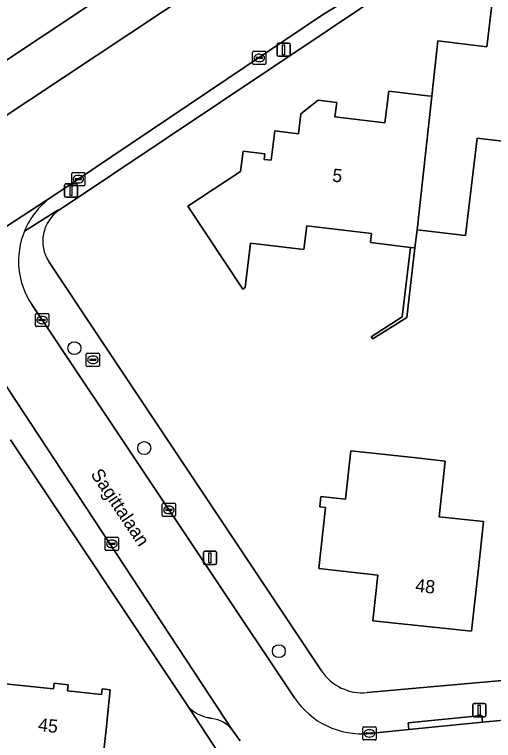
# Model space of a CAD drawing. Extents: x 162396 to 163643, y 386452 to 387406.
# Drawn here: x 163062.6 to 163098.8, y 386719.3 to 386774.2 of the extents above; entities that cross this region are included whole.
import ezdxf

# ---------------------------------------------------------------- set-up
doc = ezdxf.new("R2010")
doc.units = 0
for name, color, linetype in [('IMGEO_Boom', 7, 'Continuous'), ('IMGEO_Brandkraan', 7, 'Continuous'), ('IMGEO_Erf', 7, 'Continuous'), ('IMGEO_Kolk', 7, 'Continuous'), ('IMGEO_Lichtmast', 7, 'Continuous'), ('IMGEO_Muur', 7, 'Continuous'), ('IMGEO_Openbare_ruimte_label', 7, 'Continuous'), ('IMGEO_Pand', 7, 'Continuous'), ('IMGEO_Pand_nummerreeks', 7, 'Continuous'), ('IMGEO_Parkeervlak_open', 7, 'Continuous'), ('IMGEO_Rijbaan_lokaal_gesloten', 7, 'Continuous'), ('IMGEO_Rijbaan_lokaal_open', 7, 'Continuous'), ('IMGEO_Voetpad_open', 7, 'Continuous')]:
    doc.layers.add(name, color=color, linetype=linetype)

msp = doc.modelspace()

# ---------------------------------------------------------------- linework, layer by layer
at = {"layer": 'IMGEO_Boom'}
for centre in [(163067.103, 386748.994), (163072.383, 386741.433), (163082.556, 386726.071)]:
    msp.add_circle(centre, 0.489, dxfattribs=at)
at = {"layer": 'IMGEO_Brandkraan'}
for p, q in [((163068.004, 386747.688), (163068.004, 386748.54)), ((163068.079, 386748.614), (163068.931, 386748.614)), ((163068.263, 386748.108), (163068.263, 386748.12)), ((163068.306, 386748.157), (163068.704, 386748.157)), ((163068.492, 386748.394), (163068.517, 386748.394)), ((163068.747, 386748.12), (163068.747, 386748.108)), ((163069.005, 386748.54), (163069.005, 386747.688)), ((163068.931, 386747.614), (163068.079, 386747.614)), ((163068.701, 386748.071), (163068.303, 386748.071)), ((163068.515, 386747.834), (163068.49, 386747.834))]:
    msp.add_line(p, q, dxfattribs=at)
for points in [[(163068.004, 386747.688), (163068.004, 386748.54)], [(163068.079, 386748.614), (163068.931, 386748.614)], [(163069.005, 386748.54), (163069.005, 386747.688)], [(163068.931, 386747.614), (163068.079, 386747.614)]]:
    msp.add_lwpolyline(points, dxfattribs=at)
for centre, radius, start, end in [((163068.081, 386748.538), 0.0765, 91.552, 178.448), ((163068.081, 386748.538), 0.0765, 91.552, 178.448), ((163068.303, 386748.117), 0.0403, 85.8775, 175.7526), ((163068.3, 386748.107), 0.0366, 178.938, 274.7102), ((163068.704, 386748.114), 0.043, 264.8664, 352.4533), ((163068.708, 386748.119), 0.0386, 1.7309, 96.639), ((163068.929, 386748.538), 0.0765, 1.552, 88.448), ((163068.929, 386748.538), 0.0765, 1.552, 88.448), ((163068.081, 386747.69), 0.0765, 181.552, 268.448), ((163068.081, 386747.69), 0.0765, 181.552, 268.448), ((163068.929, 386747.69), 0.0765, 271.552, 358.448), ((163068.929, 386747.69), 0.0765, 271.552, 358.448)]:
    msp.add_arc(centre, radius, start, end, dxfattribs=at)
for centre, major_axis, ratio, start_param, end_param in [((163068.491, 386748.114), (-0.387, 0.002), 0.722429, 4.712389, 7.853982), ((163068.516, 386748.114), (-0.39, 0.002), 0.717154, 1.570796, 4.712389)]:
    msp.add_ellipse(centre, major_axis=major_axis, ratio=ratio, start_param=start_param, end_param=end_param, dxfattribs=at)
at = {"layer": 'IMGEO_Erf'}
for points in [[(162983.26, 386826.659), (162939.497, 386855.132), (162935.841, 386824.556), (162935.369, 386820.614), (162931.696, 386789.898), (162994.075, 386750), (163000, 386746.21), (163010.632, 386739.479), (163010.94, 386739.303), (163011.262, 386739.156), (163011.596, 386739.037), (163011.94, 386738.949), (163012.29, 386738.893), (163012.643, 386738.867), (163012.998, 386738.873), (163013.35, 386738.911), (163013.698, 386738.981), (163014.038, 386739.081), (163014.368, 386739.211), (163014.685, 386739.37), (163014.944, 386739.528), (163030.691, 386750), (163094.938, 386792.726)], [(163227.316, 386699.623), (163227.044, 386700.095), (163212.434, 386723.369), (163194.869, 386749.748), (163193.027, 386752.59), (163166.953, 386791.514), (163151.55, 386814.685), (163151.264, 386814.81), (163150.968, 386814.908), (163150.664, 386814.98), (163150.356, 386815.024), (163150.044, 386815.041), (163149.732, 386815.03), (163149.422, 386814.99), (163149.118, 386814.924), (163148.82, 386814.83), (163148.532, 386814.71), (163148.255, 386814.565), (163148.07, 386814.449), (163146.898, 386813.664), (163065.982, 386759.453)], [(163101.577, 386764.413), (163097.541, 386764.869), (163096.663, 386757.522), (163093.013, 386757.959), (163092.848, 386756.574), (163092.221, 386751.327), (163089.656, 386749.699), (163089.531, 386749.856), (163091.873, 386751.371), (163092.499, 386756.616), (163089.491, 386756.976), (163089.574, 386757.666), (163084.667, 386758.252), (163084.452, 386756.458), (163080.41, 386756.941), (163080.009, 386753.583), (163079.836, 386753.446), (163075.679, 386759.73), (163079.668, 386762.37), (163079.851, 386763.903), (163081.509, 386763.705), (163081.458, 386763.276), (163081.985, 386763.213), (163082.25, 386765.425), (163084.046, 386765.21), (163084.226, 386766.719), (163085.541, 386767.753), (163086.93, 386767.587), (163086.798, 386766.485), (163090.575, 386766.034), (163090.862, 386768.441), (163093.794, 386768.09), (163094.119, 386768.051), (163094.578, 386772.239), (163098.281, 386771.797), (163098.656, 386774.94)], [(163065.193, 386755.51), (163068.861, 386750), (163085.772, 386724.593)], [(163079.49, 386716.116), (163075.748, 386721.818), (163062.275, 386742.065)], [(163089.245, 386722.934), (163135.707, 386727.073)]]:
    msp.add_lwpolyline(points, dxfattribs=at)
for points in [[(163089.655, 386728.373), (163090.047, 386731.833), (163085.572, 386732.322), (163086.076, 386736.936), (163085.654, 386736.982), (163085.739, 386737.761), (163087.59, 386737.559), (163087.99, 386741.229), (163092.961, 386740.686), (163095.123, 386740.45), (163094.664, 386736.24), (163098.028, 386735.872), (163097.666, 386732.551), (163097.123, 386727.58)], [(163065.533, 386723.218), (163065.578, 386723.647), (163066.633, 386723.535), (163066.583, 386723.071), (163069.161, 386722.797), (163069.206, 386723.215), (163069.813, 386723.151), (163069.493, 386720.139), (163069.037, 386715.858), (163072.81, 386715.457), (163072.282, 386710.486), (163071.997, 386707.809), (163065.544, 386708.495), (163064.933, 386708.56), (163064.113, 386708.215), (163060.514, 386708.598), (163059.694, 386709.117), (163060.077, 386712.718), (163060.759, 386719.132), (163061.288, 386724.103), (163061.917, 386724.036), (163061.872, 386723.607)]]:
    msp.add_lwpolyline(points, close=True, dxfattribs=at)
for centre, radius, start, end in [((163067.559, 386757.087), 2.844, 123.6894, 213.6795), ((163088.899, 386726.675), 3.757, 213.6571, 275.2767)]:
    msp.add_arc(centre, radius, start, end, dxfattribs=at)
at = {"layer": 'IMGEO_Kolk'}
for p, q in [((163080.579, 386770.528), (163080.579, 386771.38)), ((163080.654, 386771.454), (163081.506, 386771.454)), ((163081.067, 386771.234), (163081.092, 386771.234)), ((163081.58, 386771.38), (163081.58, 386770.528)), ((163080.838, 386770.948), (163080.838, 386770.96)), ((163081.276, 386770.911), (163080.878, 386770.911)), ((163080.881, 386770.997), (163081.279, 386770.997)), ((163081.09, 386770.674), (163081.065, 386770.674)), ((163081.322, 386770.96), (163081.322, 386770.948)), ((163081.506, 386770.454), (163080.654, 386770.454)), ((163066.901, 386761.357), (163066.901, 386762.209)), ((163066.976, 386762.283), (163067.828, 386762.283)), ((163067.203, 386761.826), (163067.601, 386761.826)), ((163067.389, 386762.063), (163067.414, 386762.063)), ((163067.902, 386762.209), (163067.902, 386761.357)), ((163067.828, 386761.283), (163066.976, 386761.283)), ((163067.16, 386761.777), (163067.16, 386761.789)), ((163067.598, 386761.74), (163067.2, 386761.74)), ((163067.412, 386761.503), (163067.387, 386761.503)), ((163067.644, 386761.789), (163067.644, 386761.777)), ((163064.164, 386750.697), (163064.164, 386751.549)), ((163064.239, 386751.623), (163065.091, 386751.623)), ((163064.652, 386751.403), (163064.677, 386751.403)), ((163065.165, 386751.549), (163065.165, 386750.697)), ((163064.423, 386751.117), (163064.423, 386751.129)), ((163064.861, 386751.08), (163064.463, 386751.08)), ((163064.466, 386751.166), (163064.864, 386751.166)), ((163064.675, 386750.843), (163064.65, 386750.843)), ((163064.907, 386751.129), (163064.907, 386751.117)), ((163065.091, 386750.623), (163064.239, 386750.623)), ((163073.751, 386736.334), (163073.751, 386737.186)), ((163073.826, 386737.26), (163074.678, 386737.26)), ((163074.752, 386737.186), (163074.752, 386736.334)), ((163074.01, 386736.754), (163074.01, 386736.766)), ((163074.448, 386736.717), (163074.05, 386736.717)), ((163074.053, 386736.803), (163074.451, 386736.803)), ((163074.239, 386737.04), (163074.264, 386737.04)), ((163074.494, 386736.766), (163074.494, 386736.754)), ((163074.678, 386736.26), (163073.826, 386736.26)), ((163074.262, 386736.48), (163074.237, 386736.48)), ((163069.441, 386733.764), (163069.441, 386734.616)), ((163069.516, 386734.69), (163070.368, 386734.69)), ((163069.929, 386734.47), (163069.954, 386734.47)), ((163070.442, 386734.616), (163070.442, 386733.764)), ((163069.7, 386734.184), (163069.7, 386734.196)), ((163070.138, 386734.147), (163069.74, 386734.147)), ((163069.743, 386734.233), (163070.141, 386734.233)), ((163069.952, 386733.91), (163069.927, 386733.91)), ((163070.184, 386734.196), (163070.184, 386734.184)), ((163070.368, 386733.69), (163069.516, 386733.69)), ((163088.904, 386719.426), (163088.904, 386720.278)), ((163088.979, 386720.352), (163089.831, 386720.352)), ((163089.392, 386720.132), (163089.417, 386720.132)), ((163089.905, 386720.278), (163089.905, 386719.426)), ((163089.163, 386719.846), (163089.163, 386719.858)), ((163089.601, 386719.809), (163089.203, 386719.809)), ((163089.206, 386719.895), (163089.604, 386719.895)), ((163089.415, 386719.572), (163089.39, 386719.572)), ((163089.647, 386719.858), (163089.647, 386719.846)), ((163089.831, 386719.352), (163088.979, 386719.352))]:
    msp.add_line(p, q, dxfattribs=at)
for points in [[(163080.579, 386770.528), (163080.579, 386771.38)], [(163080.654, 386771.454), (163081.506, 386771.454)], [(163081.58, 386771.38), (163081.58, 386770.528)], [(163081.506, 386770.454), (163080.654, 386770.454)], [(163066.901, 386761.357), (163066.901, 386762.209)], [(163066.976, 386762.283), (163067.828, 386762.283)], [(163067.902, 386762.209), (163067.902, 386761.357)], [(163067.828, 386761.283), (163066.976, 386761.283)], [(163064.164, 386750.697), (163064.164, 386751.549)], [(163064.239, 386751.623), (163065.091, 386751.623)], [(163065.165, 386751.549), (163065.165, 386750.697)], [(163065.091, 386750.623), (163064.239, 386750.623)], [(163073.751, 386736.334), (163073.751, 386737.186)], [(163073.826, 386737.26), (163074.678, 386737.26)], [(163074.752, 386737.186), (163074.752, 386736.334)], [(163074.678, 386736.26), (163073.826, 386736.26)], [(163069.441, 386733.764), (163069.441, 386734.616)], [(163069.516, 386734.69), (163070.368, 386734.69)], [(163070.442, 386734.616), (163070.442, 386733.764)], [(163070.368, 386733.69), (163069.516, 386733.69)], [(163088.904, 386719.426), (163088.904, 386720.278)], [(163088.979, 386720.352), (163089.831, 386720.352)], [(163089.905, 386720.278), (163089.905, 386719.426)], [(163089.831, 386719.352), (163088.979, 386719.352)]]:
    msp.add_lwpolyline(points, dxfattribs=at)
for centre, radius, start, end in [((163080.656, 386771.378), 0.0765, 91.552, 178.448), ((163080.656, 386771.378), 0.0765, 91.552, 178.448), ((163081.504, 386771.378), 0.0765, 1.552, 88.448), ((163081.504, 386771.378), 0.0765, 1.552, 88.448), ((163080.878, 386770.957), 0.0403, 85.8775, 175.7526), ((163080.875, 386770.947), 0.0366, 178.938, 274.7102), ((163081.279, 386770.954), 0.043, 264.8664, 352.4533), ((163081.283, 386770.959), 0.0386, 1.7309, 96.639), ((163080.656, 386770.53), 0.0765, 181.552, 268.448), ((163080.656, 386770.53), 0.0765, 181.552, 268.448), ((163081.504, 386770.53), 0.0765, 271.552, 358.448), ((163081.504, 386770.53), 0.0765, 271.552, 358.448), ((163066.978, 386762.207), 0.0765, 91.552, 178.448), ((163066.978, 386762.207), 0.0765, 91.552, 178.448), ((163067.2, 386761.786), 0.0403, 85.8775, 175.7526), ((163067.605, 386761.788), 0.0386, 1.7309, 96.639), ((163067.826, 386762.207), 0.0765, 1.552, 88.448), ((163067.826, 386762.207), 0.0765, 1.552, 88.448), ((163066.978, 386761.359), 0.0765, 181.552, 268.448), ((163066.978, 386761.359), 0.0765, 181.552, 268.448), ((163067.197, 386761.776), 0.0366, 178.938, 274.7102), ((163067.601, 386761.783), 0.043, 264.8664, 352.4533), ((163067.826, 386761.359), 0.0765, 271.552, 358.448), ((163067.826, 386761.359), 0.0765, 271.552, 358.448), ((163064.241, 386751.547), 0.0765, 91.552, 178.448), ((163064.241, 386751.547), 0.0765, 91.552, 178.448), ((163065.089, 386751.547), 0.0765, 1.552, 88.448), ((163065.089, 386751.547), 0.0765, 1.552, 88.448), ((163064.463, 386751.126), 0.0403, 85.8775, 175.7526), ((163064.46, 386751.116), 0.0366, 178.938, 274.7102), ((163064.864, 386751.123), 0.043, 264.8664, 352.4533), ((163064.868, 386751.128), 0.0386, 1.7309, 96.639), ((163064.241, 386750.699), 0.0765, 181.552, 268.448), ((163064.241, 386750.699), 0.0765, 181.552, 268.448), ((163065.089, 386750.699), 0.0765, 271.552, 358.448), ((163065.089, 386750.699), 0.0765, 271.552, 358.448), ((163073.828, 386737.184), 0.0765, 91.552, 178.448), ((163073.828, 386737.184), 0.0765, 91.552, 178.448), ((163074.676, 386737.184), 0.0765, 1.552, 88.448), ((163074.676, 386737.184), 0.0765, 1.552, 88.448), ((163074.05, 386736.763), 0.0403, 85.8775, 175.7526), ((163074.047, 386736.753), 0.0366, 178.938, 274.7102), ((163074.451, 386736.76), 0.043, 264.8664, 352.4533), ((163074.455, 386736.765), 0.0386, 1.7309, 96.639), ((163073.828, 386736.336), 0.0765, 181.552, 268.448), ((163073.828, 386736.336), 0.0765, 181.552, 268.448), ((163074.676, 386736.336), 0.0765, 271.552, 358.448), ((163074.676, 386736.336), 0.0765, 271.552, 358.448), ((163069.518, 386734.614), 0.0765, 91.552, 178.448), ((163069.518, 386734.614), 0.0765, 91.552, 178.448), ((163070.366, 386734.614), 0.0765, 1.552, 88.448), ((163070.366, 386734.614), 0.0765, 1.552, 88.448), ((163069.74, 386734.193), 0.0403, 85.8775, 175.7526), ((163069.737, 386734.183), 0.0366, 178.938, 274.7102), ((163070.141, 386734.19), 0.043, 264.8664, 352.4533), ((163070.145, 386734.195), 0.0386, 1.7309, 96.639), ((163069.518, 386733.766), 0.0765, 181.552, 268.448), ((163069.518, 386733.766), 0.0765, 181.552, 268.448), ((163070.366, 386733.766), 0.0765, 271.552, 358.448), ((163070.366, 386733.766), 0.0765, 271.552, 358.448), ((163088.981, 386720.276), 0.0765, 91.552, 178.448), ((163088.981, 386720.276), 0.0765, 91.552, 178.448), ((163089.829, 386720.276), 0.0765, 1.552, 88.448), ((163089.829, 386720.276), 0.0765, 1.552, 88.448), ((163089.203, 386719.855), 0.0403, 85.8775, 175.7526), ((163089.2, 386719.845), 0.0366, 178.938, 274.7102), ((163089.604, 386719.852), 0.043, 264.8664, 352.4533), ((163089.608, 386719.857), 0.0386, 1.7309, 96.639), ((163088.981, 386719.428), 0.0765, 181.552, 268.448), ((163088.981, 386719.428), 0.0765, 181.552, 268.448), ((163089.829, 386719.428), 0.0765, 271.552, 358.448), ((163089.829, 386719.428), 0.0765, 271.552, 358.448)]:
    msp.add_arc(centre, radius, start, end, dxfattribs=at)
for centre, major_axis, ratio, start_param, end_param in [((163081.066, 386770.954), (-0.387, 0.002), 0.722429, 4.712389, 7.853982), ((163081.091, 386770.954), (-0.39, 0.002), 0.717154, 1.570796, 4.712389), ((163067.388, 386761.783), (-0.387, 0.002), 0.722429, 4.712389, 7.853982), ((163067.413, 386761.783), (-0.39, 0.002), 0.717154, 1.570796, 4.712389), ((163064.651, 386751.123), (-0.387, 0.002), 0.722429, 4.712389, 7.853982), ((163064.676, 386751.123), (-0.39, 0.002), 0.717154, 1.570796, 4.712389), ((163074.238, 386736.76), (-0.387, 0.002), 0.722429, 4.712389, 7.853982), ((163074.263, 386736.76), (-0.39, 0.002), 0.717154, 1.570796, 4.712389), ((163069.928, 386734.19), (-0.387, 0.002), 0.722429, 4.712389, 7.853982), ((163069.953, 386734.19), (-0.39, 0.002), 0.717154, 1.570796, 4.712389), ((163089.391, 386719.852), (-0.387, 0.002), 0.722429, 4.712389, 7.853982), ((163089.416, 386719.852), (-0.39, 0.002), 0.717154, 1.570796, 4.712389)]:
    msp.add_ellipse(centre, major_axis=major_axis, ratio=ratio, start_param=start_param, end_param=end_param, dxfattribs=at)
at = {"layer": 'IMGEO_Lichtmast'}
for p, q in [((163082.424, 386771.173), (163082.424, 386771.973)), ((163082.424, 386771.973), (163082.424, 386771.173)), ((163082.524, 386772.073), (163083.314, 386772.073)), ((163083.314, 386772.073), (163082.524, 386772.073)), ((163083.414, 386771.973), (163083.414, 386771.173)), ((163083.414, 386771.173), (163083.414, 386771.973)), ((163083.314, 386771.073), (163082.524, 386771.073)), ((163082.524, 386771.073), (163083.314, 386771.073)), ((163066.352, 386760.518), (163066.352, 386761.318)), ((163066.352, 386761.318), (163066.352, 386760.518)), ((163066.452, 386761.418), (163067.242, 386761.418)), ((163067.242, 386761.418), (163066.452, 386761.418)), ((163067.342, 386761.318), (163067.342, 386760.518)), ((163067.342, 386760.518), (163067.342, 386761.318)), ((163067.242, 386760.418), (163066.452, 386760.418)), ((163066.452, 386760.418), (163067.242, 386760.418)), ((163076.856, 386732.728), (163076.856, 386733.528)), ((163076.856, 386733.528), (163076.856, 386732.728)), ((163076.956, 386733.628), (163077.746, 386733.628)), ((163077.746, 386733.628), (163076.956, 386733.628)), ((163077.846, 386733.528), (163077.846, 386732.728)), ((163077.846, 386732.728), (163077.846, 386733.528)), ((163077.746, 386732.628), (163076.956, 386732.628)), ((163076.956, 386732.628), (163077.746, 386732.628)), ((163097.209, 386721.208), (163097.209, 386722.008)), ((163097.209, 386722.008), (163097.209, 386721.208)), ((163097.309, 386722.108), (163098.099, 386722.108)), ((163098.099, 386722.108), (163097.309, 386722.108)), ((163098.199, 386722.008), (163098.199, 386721.208)), ((163098.199, 386721.208), (163098.199, 386722.008)), ((163098.099, 386721.108), (163097.309, 386721.108)), ((163097.309, 386721.108), (163098.099, 386721.108))]:
    msp.add_line(p, q, dxfattribs=at)
for points in [[(163082.844, 386771.948), (163082.994, 386771.948), (163082.994, 386771.198), (163082.844, 386771.198), (163082.844, 386771.948)], [(163066.772, 386761.293), (163066.922, 386761.293), (163066.922, 386760.543), (163066.772, 386760.543), (163066.772, 386761.293)], [(163077.276, 386733.503), (163077.426, 386733.503), (163077.426, 386732.753), (163077.276, 386732.753), (163077.276, 386733.503)], [(163097.629, 386721.983), (163097.779, 386721.983), (163097.779, 386721.233), (163097.629, 386721.233), (163097.629, 386721.983)]]:
    msp.add_lwpolyline(points, dxfattribs=at)
for centre, start, end in [((163082.524, 386771.973), 90, 180), ((163082.524, 386771.973), 90, 180), ((163083.314, 386771.973), 0, 90), ((163083.314, 386771.973), 360, 90), ((163082.524, 386771.173), 180, 270), ((163082.524, 386771.173), 180, 270), ((163083.314, 386771.173), 270, 0), ((163083.314, 386771.173), 270, 0), ((163066.452, 386761.318), 90, 180), ((163066.452, 386761.318), 90, 180), ((163067.242, 386761.318), 0, 90), ((163067.242, 386761.318), 360, 90), ((163066.452, 386760.518), 180, 270), ((163066.452, 386760.518), 180, 270), ((163067.242, 386760.518), 270, 0), ((163067.242, 386760.518), 270, 0), ((163076.956, 386733.528), 90, 180), ((163076.956, 386733.528), 90, 180), ((163077.746, 386733.528), 0, 90), ((163077.746, 386733.528), 360, 90), ((163076.956, 386732.728), 180, 270), ((163076.956, 386732.728), 180, 270), ((163077.746, 386732.728), 270, 0), ((163077.746, 386732.728), 270, 0), ((163097.309, 386722.008), 90, 180), ((163097.309, 386722.008), 90, 180), ((163098.099, 386722.008), 0, 90), ((163098.099, 386722.008), 360, 90), ((163097.309, 386721.208), 180, 270), ((163097.309, 386721.208), 180, 270), ((163098.099, 386721.208), 270, 0), ((163098.099, 386721.208), 270, 0)]:
    msp.add_arc(centre, 0.1, start, end, dxfattribs=at)
at = {"layer": 'IMGEO_Muur'}
msp.add_lwpolyline([(163092.499, 386756.616), (163091.873, 386751.371), (163089.531, 386749.856), (163089.656, 386749.699), (163092.221, 386751.327), (163092.848, 386756.574)], close=True, dxfattribs=at)
at = {"layer": 'IMGEO_Pand'}
for points in [[(163106.471, 386773.435), (163106.653, 386775.013), (163106.299, 386775.054), (163102.972, 386775.438), (163103.01, 386775.768), (163102.569, 386775.819), (163102.434, 386774.504), (163098.916, 386774.91), (163098.656, 386774.94), (163098.281, 386771.797), (163094.578, 386772.239), (163094.119, 386768.051), (163093.013, 386757.959), (163096.663, 386757.522), (163097.541, 386764.869), (163101.577, 386764.413), (163101.649, 386765.034), (163105.449, 386764.595)], [(163094.119, 386768.051), (163093.794, 386768.09), (163090.862, 386768.441), (163090.575, 386766.034), (163086.798, 386766.485), (163086.93, 386767.587), (163085.541, 386767.753), (163084.226, 386766.719), (163084.046, 386765.21), (163082.25, 386765.425), (163081.985, 386763.213), (163081.458, 386763.276), (163081.509, 386763.705), (163079.851, 386763.903), (163079.668, 386762.37), (163075.679, 386759.73), (163079.836, 386753.446), (163080.009, 386753.583), (163080.41, 386756.941), (163084.452, 386756.458), (163084.667, 386758.252), (163089.574, 386757.666), (163089.491, 386756.976), (163092.499, 386756.616), (163092.848, 386756.574), (163093.013, 386757.959)], [(163097.666, 386732.551), (163098.028, 386735.872), (163094.664, 386736.24), (163095.123, 386740.45), (163092.961, 386740.686), (163087.99, 386741.229), (163087.59, 386737.559), (163085.739, 386737.761), (163085.654, 386736.982), (163086.076, 386736.936), (163085.572, 386732.322), (163090.047, 386731.833), (163089.655, 386728.373), (163097.123, 386727.58)], [(163069.493, 386720.139), (163069.813, 386723.151), (163069.206, 386723.215), (163069.161, 386722.797), (163066.583, 386723.071), (163066.633, 386723.535), (163065.578, 386723.647), (163065.533, 386723.218), (163061.872, 386723.607), (163061.917, 386724.036), (163061.288, 386724.103), (163060.759, 386719.132), (163060.077, 386712.718), (163059.694, 386709.117), (163060.514, 386708.598), (163064.113, 386708.215), (163064.933, 386708.56), (163065.544, 386708.495), (163071.997, 386707.809), (163072.282, 386710.486), (163072.81, 386715.457), (163069.037, 386715.858)]]:
    msp.add_lwpolyline(points, close=True, dxfattribs=at)
at = {"layer": 'IMGEO_Parkeervlak_open'}
for points in [[(163079.033, 386720.129), (163062.126, 386745.866)], [(163062.275, 386742.065), (163075.748, 386721.818)], [(163077.165, 386721.061), (163077.504, 386720.979)]]:
    msp.add_lwpolyline(points, dxfattribs=at)
for centre, radius, start, end in [((163077.682, 386723.734), 2.722, 224.7247, 259.0506), ((163077.21, 386718.649), 2.348, 39.0614, 82.7975)]:
    msp.add_arc(centre, radius, start, end, dxfattribs=at)
at = {"layer": 'IMGEO_Rijbaan_lokaal_gesloten'}
msp.add_lwpolyline([(163065.539, 386760.542), (163085.934, 386774.259), (163087.891, 386775.462), (163086.931, 386776.836), (163084.887, 386779.893), (163084.016, 386781.282), (163053.527, 386761.018), (163044.946, 386755.247), (163037.12, 386750.107), (163027.385, 386743.673), (163022.823, 386740.671), (163021.049, 386739.492), (163020.532, 386739.148), (163018.704, 386737.897), (163022.574, 386732.192), (163024.659, 386733.665), (163043.288, 386745.904), (163047.031, 386748.398), (163049.437, 386750), (163051.556, 386751.416), (163051.609, 386751.451), (163051.663, 386751.486)], close=True, dxfattribs=at)
at = {"layer": 'IMGEO_Rijbaan_lokaal_open'}
for points in [[(163065.539, 386760.542), (163051.663, 386751.486)], [(163083.743, 386722.54), (163065.412, 386750), (163063.882, 386752.292)], [(163059.121, 386750.304), (163059.355, 386750), (163061.185, 386747.272), (163062.126, 386745.866), (163079.033, 386720.129), (163079.637, 386719.279)], [(163141.811, 386723.064), (163140.884, 386723.484), (163139.923, 386723.819), (163138.936, 386724.066), (163137.931, 386724.225), (163136.916, 386724.293), (163135.898, 386724.271), (163135.635, 386724.25), (163133.912, 386724.09), (163118.21, 386722.627), (163114.218, 386722.255), (163112.236, 386722.066), (163097.959, 386720.704), (163092.387, 386720.148), (163089.401, 386719.85)]]:
    msp.add_lwpolyline(points, dxfattribs=at)
for centre, radius, start, end in [((163068.818, 386755.596), 5.935, 123.5452, 157.6653), ((163068.828, 386755.591), 5.946, 157.6605, 213.7015), ((163088.823, 386725.929), 6.107, 213.7102, 275.4339)]:
    msp.add_arc(centre, radius, start, end, dxfattribs=at)
at = {"layer": 'IMGEO_Voetpad_open'}
for points in [[(163146.898, 386813.664), (163146.295, 386814.578), (163146.086, 386814.438), (163133.018, 386805.708), (163133.284, 386805.286), (163128.965, 386802.433), (163128.699, 386802.855), (163128.182, 386802.509), (163114.647, 386793.426), (163112.536, 386792.008), (163087.891, 386775.462), (163085.934, 386774.259), (163065.539, 386760.542)], [(163063.329, 386757.851), (163065.864, 386759.423), (163065.982, 386759.453), (163146.898, 386813.664)], [(163090.874, 386798.95), (163094.938, 386792.726), (163030.691, 386750), (163014.944, 386739.528), (163010.346, 386735.997)], [(163016.013, 386736.331), (163018.704, 386737.897), (163020.532, 386739.148), (163021.049, 386739.492), (163022.823, 386740.671), (163027.385, 386743.673), (163037.12, 386750.107), (163044.946, 386755.247), (163053.527, 386761.018), (163084.016, 386781.282)], [(163065.982, 386759.453), (163065.864, 386759.423), (163063.329, 386757.851)], [(163085.772, 386724.593), (163068.861, 386750), (163065.193, 386755.51)], [(163063.882, 386752.292), (163065.412, 386750), (163083.743, 386722.54)], [(163135.707, 386727.073), (163089.245, 386722.934)], [(163089.401, 386719.85), (163092.387, 386720.148), (163092.338, 386720.645), (163097.91, 386721.202), (163097.959, 386720.704), (163112.236, 386722.066), (163112.19, 386722.563), (163118.164, 386723.124), (163118.21, 386722.627), (163133.912, 386724.09), (163133.881, 386724.589), (163135.59, 386724.748), (163135.762, 386724.762), (163136.823, 386724.795), (163137.884, 386724.733), (163138.934, 386724.577), (163139.967, 386724.327), (163140.973, 386723.986), (163141.944, 386723.557), (163141.811, 386723.064)], [(163075.748, 386721.818), (163079.49, 386716.116)], [(163077.504, 386720.979), (163077.165, 386721.061)], [(163079.637, 386719.279), (163079.033, 386720.129)]]:
    msp.add_lwpolyline(points, dxfattribs=at)
msp.add_lwpolyline([(163097.959, 386720.704), (163097.91, 386721.202), (163092.338, 386720.645), (163092.387, 386720.148)], close=True, dxfattribs=at)
for centre, radius, start, end in [((163068.818, 386755.596), 5.935, 123.5452, 157.6653), ((163067.559, 386757.087), 2.844, 123.6894, 213.6795), ((163068.828, 386755.591), 5.946, 157.6605, 213.7015), ((163088.899, 386726.675), 3.757, 213.6571, 275.2767), ((163088.823, 386725.929), 6.107, 213.7102, 275.4339), ((163077.682, 386723.734), 2.722, 224.7247, 259.0506), ((163077.21, 386718.649), 2.348, 39.0614, 82.7975)]:
    msp.add_arc(centre, radius, start, end, dxfattribs=at)

# ---------------------------------------------------------------- texts
at = {"layer": 'IMGEO_Openbare_ruimte_label'}
msp.add_text('Sagittalaan', height=1, rotation=303.7854, dxfattribs=at).set_placement((163068.297, 386739.46))
at = {"layer": 'IMGEO_Pand_nummerreeks'}
for s, rotation, p in [('5', 353.1761, (163086.553, 386761.606)), ('48', 353.9387, (163092.837, 386730.569)), ('45', 353.6975, (163064.324, 386720.035))]:
    msp.add_text(s, height=1, rotation=rotation, dxfattribs=at).set_placement(p)

doc.saveas('drawing.dxf')
